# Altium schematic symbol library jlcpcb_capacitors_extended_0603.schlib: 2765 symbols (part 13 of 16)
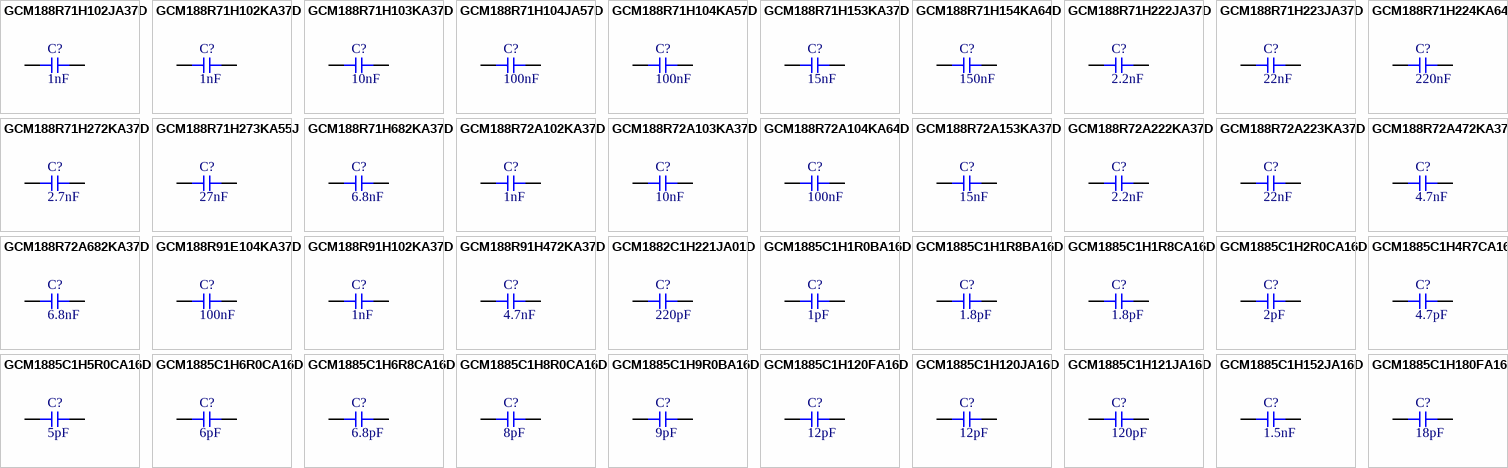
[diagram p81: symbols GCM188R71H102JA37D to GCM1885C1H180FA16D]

## GCM1885C1H152JA16D
designator C?  Capacitance: 1.5nF  (hidden comment: *)
Capacitor, Ceramic (MLCC), 1.5nF, ±5%, 50V, C0G, ±5%, SMD 0603; Manufacturer: Murata Electronics; Manufacturer Part Number: GCM1885C1H152JA16D
footprint CAP-0603 (0603 (1608M) Capacitor)
pins: 1, 2

## GCM1885C1H180FA16D
designator C?  Capacitance: 18pF  (hidden comment: *)
Capacitor, Ceramic (MLCC), 18pF, ±1%, 50V, C0G, ±1%, SMD 0603; Manufacturer: Murata Electronics; Manufacturer Part Number: GCM1885C1H180FA16D
footprint CAP-0603 (0603 (1608M) Capacitor)
pins: 1, 2

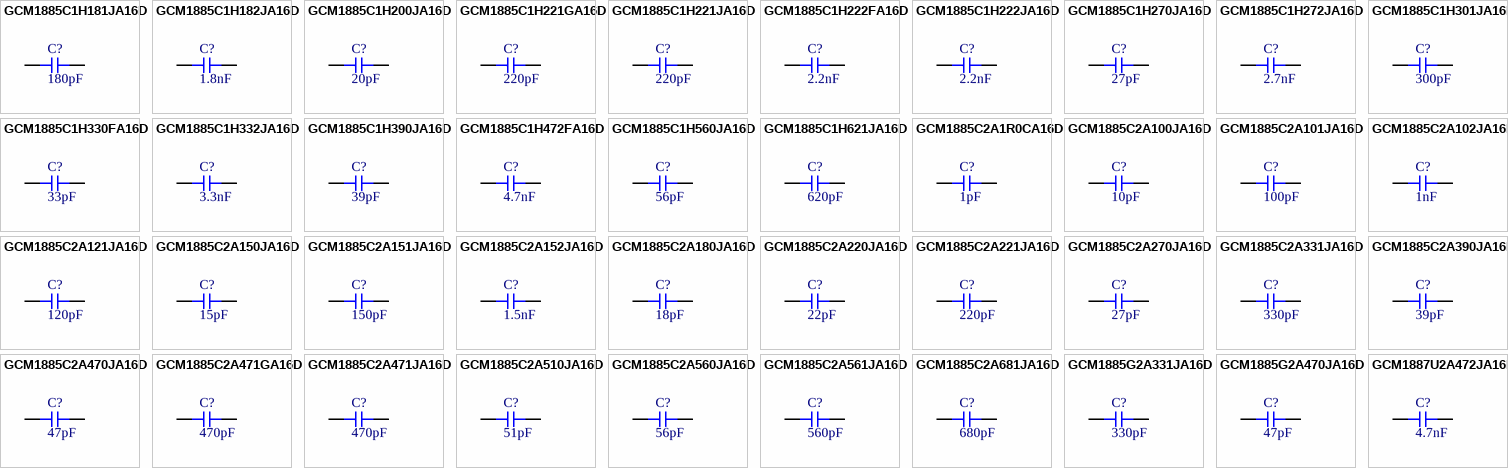
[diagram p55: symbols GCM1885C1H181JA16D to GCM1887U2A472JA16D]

## GCM1885C1H181JA16D
designator C?  Capacitance: 180pF  (hidden comment: *)
Capacitor, Ceramic (MLCC), 180pF, ±5%, 50V, C0G, ±5%, SMD 0603; Manufacturer: Murata Electronics; Manufacturer Part Number: GCM1885C1H181JA16D
footprint CAP-0603 (0603 (1608M) Capacitor)
pins: 1, 2

## GCM1885C1H182JA16D
designator C?  Capacitance: 1.8nF  (hidden comment: *)
Capacitor, Ceramic (MLCC), 1.8nF, ±5%, 50V, C0G, ±5%, SMD 0603; Manufacturer: Murata Electronics; Manufacturer Part Number: GCM1885C1H182JA16D
footprint CAP-0603 (0603 (1608M) Capacitor)
pins: 1, 2

## GCM1885C1H200JA16D
designator C?  Capacitance: 20pF  (hidden comment: *)
Capacitor, Ceramic (MLCC), 20pF, ±5%, 50V, C0G, ±5%, SMD 0603; Manufacturer: Murata Electronics; Manufacturer Part Number: GCM1885C1H200JA16D
footprint CAP-0603 (0603 (1608M) Capacitor)
pins: 1, 2

## GCM1885C1H221GA16D
designator C?  Capacitance: 220pF  (hidden comment: *)
Capacitor, Ceramic (MLCC), 220pF, ±2%, 50V, C0G, ±2%, SMD 0603; Manufacturer: Murata Electronics; Manufacturer Part Number: GCM1885C1H221GA16D
footprint CAP-0603 (0603 (1608M) Capacitor)
pins: 1, 2

## GCM1885C1H221JA16D
designator C?  Capacitance: 220pF  (hidden comment: *)
Capacitor, Ceramic (MLCC), 220pF, ±5%, 50V, C0G, ±5%, SMD 0603; Manufacturer: Murata Electronics; Manufacturer Part Number: GCM1885C1H221JA16D
footprint CAP-0603 (0603 (1608M) Capacitor)
pins: 1, 2

## GCM1885C1H222FA16D
designator C?  Capacitance: 2.2nF  (hidden comment: *)
Capacitor, Ceramic (MLCC), 2.2nF, ±1%, ±1%, SMD 0603; Manufacturer: Murata Electronics; Manufacturer Part Number: GCM1885C1H222FA16D
footprint CAP-0603 (0603 (1608M) Capacitor)
pins: 1, 2

## GCM1885C1H222JA16D
designator C?  Capacitance: 2.2nF  (hidden comment: *)
Capacitor, Ceramic (MLCC), 2.2nF, ±5%, 50V, C0G, ±5%, SMD 0603; Manufacturer: Murata Electronics; Manufacturer Part Number: GCM1885C1H222JA16D
footprint CAP-0603 (0603 (1608M) Capacitor)
pins: 1, 2

## GCM1885C1H270JA16D
designator C?  Capacitance: 27pF  (hidden comment: *)
Capacitor, Ceramic (MLCC), 27pF, ±5%, 50V, C0G, ±5%, SMD 0603; Manufacturer: Murata Electronics; Manufacturer Part Number: GCM1885C1H270JA16D
footprint CAP-0603 (0603 (1608M) Capacitor)
pins: 1, 2

## GCM1885C1H272JA16D
designator C?  Capacitance: 2.7nF  (hidden comment: *)
Capacitor, Ceramic (MLCC), 2.7nF, ±5%, 50V, C0G, ±5%, SMD 0603; Manufacturer: Murata Electronics; Manufacturer Part Number: GCM1885C1H272JA16D
footprint CAP-0603 (0603 (1608M) Capacitor)
pins: 1, 2

## GCM1885C1H301JA16D
designator C?  Capacitance: 300pF  (hidden comment: *)
Capacitor, Ceramic (MLCC), 300pF, ±5%, ±5%, SMD 0603; Manufacturer: Murata Electronics; Manufacturer Part Number: GCM1885C1H301JA16D
footprint CAP-0603 (0603 (1608M) Capacitor)
pins: 1, 2

## GCM1885C1H330FA16D
designator C?  Capacitance: 33pF  (hidden comment: *)
Capacitor, Ceramic (MLCC), 33pF, ±1%, 50V, C0G, ±1%, SMD 0603; Manufacturer: Murata Electronics; Manufacturer Part Number: GCM1885C1H330FA16D
footprint CAP-0603 (0603 (1608M) Capacitor)
pins: 1, 2

## GCM1885C1H332JA16D
designator C?  Capacitance: 3.3nF  (hidden comment: *)
Capacitor, Ceramic (MLCC), 3.3nF, ±5%, 50V, C0G, ±5%, SMD 0603; Manufacturer: Murata Electronics; Manufacturer Part Number: GCM1885C1H332JA16D
footprint CAP-0603 (0603 (1608M) Capacitor)
pins: 1, 2

## GCM1885C1H390JA16D
designator C?  Capacitance: 39pF  (hidden comment: *)
Capacitor, Ceramic (MLCC), 39pF, ±5%, 50V, C0G, ±5%, SMD 0603; Manufacturer: Murata Electronics; Manufacturer Part Number: GCM1885C1H390JA16D
footprint CAP-0603 (0603 (1608M) Capacitor)
pins: 1, 2

## GCM1885C1H472FA16D
designator C?  Capacitance: 4.7nF  (hidden comment: *)
Capacitor, Ceramic (MLCC), 4.7nF, ±1%, ±1%, SMD 0603; Manufacturer: Murata Electronics; Manufacturer Part Number: GCM1885C1H472FA16D
footprint CAP-0603 (0603 (1608M) Capacitor)
pins: 1, 2

## GCM1885C1H560JA16D
designator C?  Capacitance: 56pF  (hidden comment: *)
Capacitor, Ceramic (MLCC), 56pF, ±5%, 50V, C0G, ±5%, SMD 0603; Manufacturer: Murata Electronics; Manufacturer Part Number: GCM1885C1H560JA16D
footprint CAP-0603 (0603 (1608M) Capacitor)
pins: 1, 2

## GCM1885C1H621JA16D
designator C?  Capacitance: 620pF  (hidden comment: *)
Capacitor, Ceramic (MLCC), 620pF, ±5%, 50V, C0G, ±5%, SMD 0603; Manufacturer: Murata Electronics; Manufacturer Part Number: GCM1885C1H621JA16D
footprint CAP-0603 (0603 (1608M) Capacitor)
pins: 1, 2

## GCM1885C2A1R0CA16D
designator C?  Capacitance: 1pF  (hidden comment: *)
Capacitor, Ceramic (MLCC), 1pF, ±0.25pF, 100V, C0G, ±0.25pF, SMD 0603; Manufacturer: Murata Electronics; Manufacturer Part Number: GCM1885C2A1R0CA16D
footprint CAP-0603 (0603 (1608M) Capacitor)
pins: 1, 2

## GCM1885C2A100JA16D
designator C?  Capacitance: 10pF  (hidden comment: *)
Capacitor, Ceramic (MLCC), 10pF, ±5%, 100V, C0G, ±5%, SMD 0603; Manufacturer: Murata Electronics; Manufacturer Part Number: GCM1885C2A100JA16D
footprint CAP-0603 (0603 (1608M) Capacitor)
pins: 1, 2

## GCM1885C2A101JA16D
designator C?  Capacitance: 100pF  (hidden comment: *)
Capacitor, Ceramic (MLCC), 100pF, ±5%, 100V, C0G, ±5%, SMD 0603; Manufacturer: Murata Electronics; Manufacturer Part Number: GCM1885C2A101JA16D
footprint CAP-0603 (0603 (1608M) Capacitor)
pins: 1, 2

## GCM1885C2A102JA16D
designator C?  Capacitance: 1nF  (hidden comment: *)
Capacitor, Ceramic (MLCC), 1nF, ±5%, 100V, C0G, ±5%, SMD 0603; Manufacturer: Murata Electronics; Manufacturer Part Number: GCM1885C2A102JA16D
footprint CAP-0603 (0603 (1608M) Capacitor)
pins: 1, 2

## GCM1885C2A121JA16D
designator C?  Capacitance: 120pF  (hidden comment: *)
Capacitor, Ceramic (MLCC), 120pF, ±5%, ±5%, SMD 0603; Manufacturer: Murata Electronics; Manufacturer Part Number: GCM1885C2A121JA16D
footprint CAP-0603 (0603 (1608M) Capacitor)
pins: 1, 2

## GCM1885C2A150JA16D
designator C?  Capacitance: 15pF  (hidden comment: *)
Capacitor, Ceramic (MLCC), 15pF, ±5%, 100V, C0G, ±5%, SMD 0603; Manufacturer: Murata Electronics; Manufacturer Part Number: GCM1885C2A150JA16D
footprint CAP-0603 (0603 (1608M) Capacitor)
pins: 1, 2

## GCM1885C2A151JA16D
designator C?  Capacitance: 150pF  (hidden comment: *)
Capacitor, Ceramic (MLCC), 150pF, ±5%, 100V, C0G, ±5%, SMD 0603; Manufacturer: Murata Electronics; Manufacturer Part Number: GCM1885C2A151JA16D
footprint CAP-0603 (0603 (1608M) Capacitor)
pins: 1, 2

## GCM1885C2A152JA16D
designator C?  Capacitance: 1.5nF  (hidden comment: *)
Capacitor, Ceramic (MLCC), 1.5nF, ±5%, 100V, C0G, ±5%, SMD 0603; Manufacturer: Murata Electronics; Manufacturer Part Number: GCM1885C2A152JA16D
footprint CAP-0603 (0603 (1608M) Capacitor)
pins: 1, 2

## GCM1885C2A180JA16D
designator C?  Capacitance: 18pF  (hidden comment: *)
Capacitor, Ceramic (MLCC), 18pF, ±5%, ±5%, SMD 0603; Manufacturer: Murata Electronics; Manufacturer Part Number: GCM1885C2A180JA16D
footprint CAP-0603 (0603 (1608M) Capacitor)
pins: 1, 2

## GCM1885C2A220JA16D
designator C?  Capacitance: 22pF  (hidden comment: *)
Capacitor, Ceramic (MLCC), 22pF, ±5%, 100V, C0G, ±5%, SMD 0603; Manufacturer: Murata Electronics; Manufacturer Part Number: GCM1885C2A220JA16D
footprint CAP-0603 (0603 (1608M) Capacitor)
pins: 1, 2

## GCM1885C2A221JA16D
designator C?  Capacitance: 220pF  (hidden comment: *)
Capacitor, Ceramic (MLCC), 220pF, ±5%, 100V, C0G, ±5%, SMD 0603; Manufacturer: Murata Electronics; Manufacturer Part Number: GCM1885C2A221JA16D
footprint CAP-0603 (0603 (1608M) Capacitor)
pins: 1, 2

## GCM1885C2A270JA16D
designator C?  Capacitance: 27pF  (hidden comment: *)
Capacitor, Ceramic (MLCC), 27pF, ±5%, ±5%, SMD 0603; Manufacturer: Murata Electronics; Manufacturer Part Number: GCM1885C2A270JA16D
footprint CAP-0603 (0603 (1608M) Capacitor)
pins: 1, 2

## GCM1885C2A331JA16D
designator C?  Capacitance: 330pF  (hidden comment: *)
Capacitor, Ceramic (MLCC), 330pF, ±5%, 100V, C0G, ±5%, SMD 0603; Manufacturer: Murata Electronics; Manufacturer Part Number: GCM1885C2A331JA16D
footprint CAP-0603 (0603 (1608M) Capacitor)
pins: 1, 2

## GCM1885C2A390JA16D
designator C?  Capacitance: 39pF  (hidden comment: *)
Capacitor, Ceramic (MLCC), 39pF, ±5%, 100V, C0G, ±5%, SMD 0603; Manufacturer: Murata Electronics; Manufacturer Part Number: GCM1885C2A390JA16D
footprint CAP-0603 (0603 (1608M) Capacitor)
pins: 1, 2

## GCM1885C2A470JA16D
designator C?  Capacitance: 47pF  (hidden comment: *)
Capacitor, Ceramic (MLCC), 47pF, ±5%, 100V, C0G, ±5%, SMD 0603; Manufacturer: Murata Electronics; Manufacturer Part Number: GCM1885C2A470JA16D
footprint CAP-0603 (0603 (1608M) Capacitor)
pins: 1, 2

## GCM1885C2A471GA16D
designator C?  Capacitance: 470pF  (hidden comment: *)
Capacitor, Ceramic (MLCC), 470pF, ±2%, 100V, C0G, ±2%, SMD 0603; Manufacturer: Murata Electronics; Manufacturer Part Number: GCM1885C2A471GA16D
footprint CAP-0603 (0603 (1608M) Capacitor)
pins: 1, 2

## GCM1885C2A471JA16D
designator C?  Capacitance: 470pF  (hidden comment: *)
Capacitor, Ceramic (MLCC), 470pF, ±5%, 100V, C0G, ±5%, SMD 0603; Manufacturer: Murata Electronics; Manufacturer Part Number: GCM1885C2A471JA16D
footprint CAP-0603 (0603 (1608M) Capacitor)
pins: 1, 2

## GCM1885C2A510JA16D
designator C?  Capacitance: 51pF  (hidden comment: *)
Capacitor, Ceramic (MLCC), 51pF, ±5%, 100V, C0G, ±5%, SMD 0603; Manufacturer: Murata Electronics; Manufacturer Part Number: GCM1885C2A510JA16D
footprint CAP-0603 (0603 (1608M) Capacitor)
pins: 1, 2

## GCM1885C2A560JA16D
designator C?  Capacitance: 56pF  (hidden comment: *)
Capacitor, Ceramic (MLCC), 56pF, ±5%, 100V, C0G, ±5%, SMD 0603; Manufacturer: Murata Electronics; Manufacturer Part Number: GCM1885C2A560JA16D
footprint CAP-0603 (0603 (1608M) Capacitor)
pins: 1, 2

## GCM1885C2A561JA16D
designator C?  Capacitance: 560pF  (hidden comment: *)
Capacitor, Ceramic (MLCC), 560pF, ±5%, 100V, C0G, ±5%, SMD 0603; Manufacturer: Murata Electronics; Manufacturer Part Number: GCM1885C2A561JA16D
footprint CAP-0603 (0603 (1608M) Capacitor)
pins: 1, 2

## GCM1885C2A681JA16D
designator C?  Capacitance: 680pF  (hidden comment: *)
Capacitor, Ceramic (MLCC), 680pF, ±5%, 100V, C0G, ±5%, SMD 0603; Manufacturer: Murata Electronics; Manufacturer Part Number: GCM1885C2A681JA16D
footprint CAP-0603 (0603 (1608M) Capacitor)
pins: 1, 2

## GCM1885G2A331JA16D
designator C?  Capacitance: 330pF  (hidden comment: *)
Capacitor, Ceramic (MLCC), 330pF, ±5%, 100V, X8G, ±5%, SMD 0603; Manufacturer: Murata Electronics; Manufacturer Part Number: GCM1885G2A331JA16D
footprint CAP-0603 (0603 (1608M) Capacitor)
pins: 1, 2

## GCM1885G2A470JA16D
designator C?  Capacitance: 47pF  (hidden comment: *)
Capacitor, Ceramic (MLCC), 47pF, ±5%, 100V, X8G, ±5%, SMD 0603; Manufacturer: Murata Electronics; Manufacturer Part Number: GCM1885G2A470JA16D
footprint CAP-0603 (0603 (1608M) Capacitor)
pins: 1, 2

## GCM1887U2A472JA16D
designator C?  Capacitance: 4.7nF  (hidden comment: *)
Capacitor, Ceramic (MLCC), 4.7nF, ±5%, ±5%, SMD 0603; Manufacturer: Murata Electronics; Manufacturer Part Number: GCM1887U2A472JA16D
footprint CAP-0603 (0603 (1608M) Capacitor)
pins: 1, 2

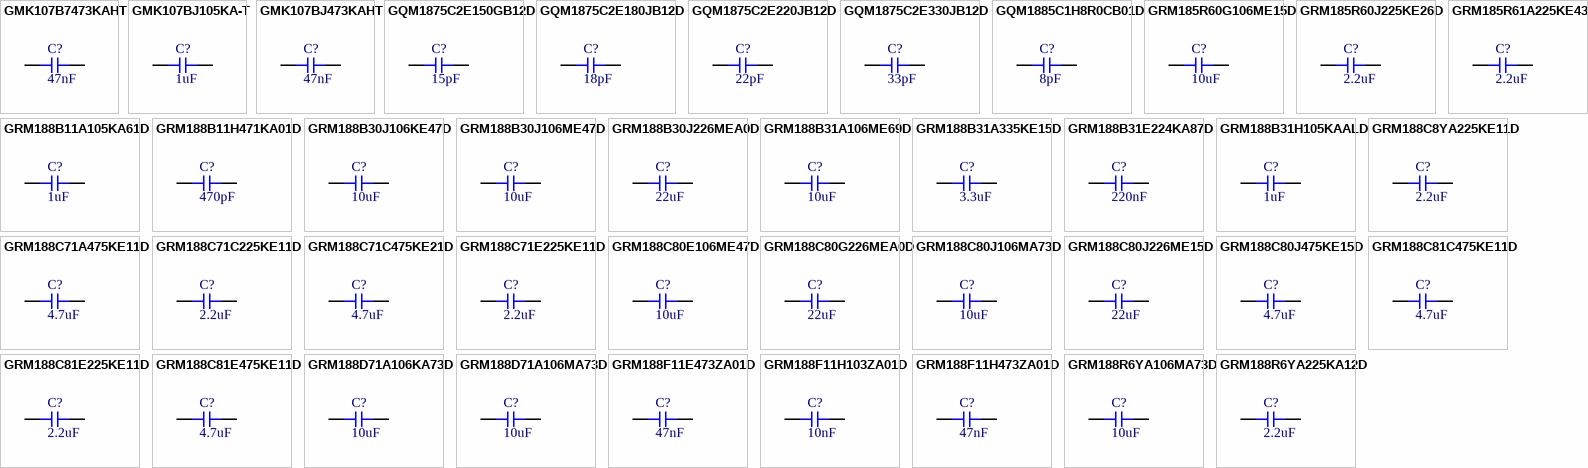
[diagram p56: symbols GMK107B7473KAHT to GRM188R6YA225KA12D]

## GMK107B7473KAHT
designator C?  Capacitance: 47nF  (hidden comment: *)
Capacitor, Ceramic (MLCC), 47nF, ±10%, 35V, X7R, ±10%, SMD 0603; Manufacturer: Taiyo Yuden; Manufacturer Part Number: GMK107B7473KAHT
footprint CAP-0603 (0603 (1608M) Capacitor)
pins: 1, 2

## GMK107BJ105KA-T
designator C?  Capacitance: 1uF  (hidden comment: *)
Capacitor, Ceramic (MLCC), 1uF, ±10%, 35V, X5R, ±10%, SMD 0603; Manufacturer: Taiyo Yuden; Manufacturer Part Number: GMK107BJ105KA-T
footprint CAP-0603 (0603 (1608M) Capacitor)
pins: 1, 2

## GMK107BJ473KAHT
designator C?  Capacitance: 47nF  (hidden comment: *)
Capacitor, Ceramic (MLCC), 47nF, ±10%, 35V, X5R, ±10%, SMD 0603; Manufacturer: Taiyo Yuden; Manufacturer Part Number: GMK107BJ473KAHT
footprint CAP-0603 (0603 (1608M) Capacitor)
pins: 1, 2

## GQM1875C2E150GB12D
designator C?  Capacitance: 15pF  (hidden comment: *)
Capacitor, Ceramic (MLCC), 15pF, ±2%, 250V, C0G, ±2%, SMD 0603; Manufacturer: Murata Electronics; Manufacturer Part Number: GQM1875C2E150GB12D
footprint CAP-0603 (0603 (1608M) Capacitor)
pins: 1, 2

## GQM1875C2E180JB12D
designator C?  Capacitance: 18pF  (hidden comment: *)
Capacitor, Ceramic (MLCC), 18pF, ±5%, 250V, C0G, ±5%, SMD 0603; Manufacturer: Murata Electronics; Manufacturer Part Number: GQM1875C2E180JB12D
footprint CAP-0603 (0603 (1608M) Capacitor)
pins: 1, 2

## GQM1875C2E220JB12D
designator C?  Capacitance: 22pF  (hidden comment: *)
Capacitor, Ceramic (MLCC), 22pF, ±5%, 250V, C0G, ±5%, SMD 0603; Manufacturer: Murata Electronics; Manufacturer Part Number: GQM1875C2E220JB12D
footprint CAP-0603 (0603 (1608M) Capacitor)
pins: 1, 2

## GQM1875C2E330JB12D
designator C?  Capacitance: 33pF  (hidden comment: *)
Capacitor, Ceramic (MLCC), 33pF, ±5%, ±5%, SMD 0603; Manufacturer: Murata Electronics; Manufacturer Part Number: GQM1875C2E330JB12D
footprint CAP-0603 (0603 (1608M) Capacitor)
pins: 1, 2

## GQM1885C1H8R0CB01D
designator C?  Capacitance: 8pF  (hidden comment: *)
Capacitor, Ceramic (MLCC), 8pF, ±0.25pF, 50V, C0G, ±0.25pF, SMD 0603; Manufacturer: Murata Electronics; Manufacturer Part Number: GQM1885C1H8R0CB01D
footprint CAP-0603 (0603 (1608M) Capacitor)
pins: 1, 2

## GRM185R60G106ME15D
designator C?  Capacitance: 10uF  (hidden comment: *)
Capacitor, Ceramic (MLCC), 10uF, ±20%, ±20%, SMD 0603; Manufacturer: Murata Electronics; Manufacturer Part Number: GRM185R60G106ME15D
footprint CAP-0603 (0603 (1608M) Capacitor)
pins: 1, 2

## GRM185R60J225KE26D
designator C?  Capacitance: 2.2uF  (hidden comment: *)
Capacitor, Ceramic (MLCC), 2.2uF, ±10%, ±10%, SMD 0603; Manufacturer: Murata Electronics; Manufacturer Part Number: GRM185R60J225KE26D
footprint CAP-0603 (0603 (1608M) Capacitor)
pins: 1, 2

## GRM185R61A225KE43D
designator C?  Capacitance: 2.2uF  (hidden comment: *)
Capacitor, Ceramic (MLCC), 2.2uF, ±10%, 10V, X5R, ±10%, SMD 0603; Manufacturer: Murata Electronics; Manufacturer Part Number: GRM185R61A225KE43D
footprint CAP-0603 (0603 (1608M) Capacitor)
pins: 1, 2

## GRM188B11A105KA61D
designator C?  Capacitance: 1uF  (hidden comment: *)
Capacitor, Ceramic (MLCC), 1uF, ±10%, 10V, B, ±10%, SMD 0603; Manufacturer: Murata Electronics; Manufacturer Part Number: GRM188B11A105KA61D
footprint CAP-0603 (0603 (1608M) Capacitor)
pins: 1, 2

## GRM188B11H471KA01D
designator C?  Capacitance: 470pF  (hidden comment: *)
Capacitor, Ceramic (MLCC), 470pF, ±10%, 50V, B, ±10%, SMD 0603; Manufacturer: Murata Electronics; Manufacturer Part Number: GRM188B11H471KA01D
footprint CAP-0603 (0603 (1608M) Capacitor)
pins: 1, 2

## GRM188B30J106KE47D
designator C?  Capacitance: 10uF  (hidden comment: *)
Capacitor, Ceramic (MLCC), 10uF, ±10%, 6.3V, B, ±10%, SMD 0603; Manufacturer: Murata Electronics; Manufacturer Part Number: GRM188B30J106KE47D
footprint CAP-0603 (0603 (1608M) Capacitor)
pins: 1, 2

## GRM188B30J106ME47D
designator C?  Capacitance: 10uF  (hidden comment: *)
Capacitor, Ceramic (MLCC), 10uF, ±20%, 6.3V, B, ±20%, SMD 0603; Manufacturer: Murata Electronics; Manufacturer Part Number: GRM188B30J106ME47D
footprint CAP-0603 (0603 (1608M) Capacitor)
pins: 1, 2

## GRM188B30J226MEA0D
designator C?  Capacitance: 22uF  (hidden comment: *)
Capacitor, Ceramic (MLCC), 22uF, ±20%, 6.3V, B, ±20%, SMD 0603; Manufacturer: Murata Electronics; Manufacturer Part Number: GRM188B30J226MEA0D
footprint CAP-0603 (0603 (1608M) Capacitor)
pins: 1, 2

## GRM188B31A106ME69D
designator C?  Capacitance: 10uF  (hidden comment: *)
Capacitor, Ceramic (MLCC), 10uF, ±20%, 10V, B, ±20%, SMD 0603; Manufacturer: Murata Electronics; Manufacturer Part Number: GRM188B31A106ME69D
footprint CAP-0603 (0603 (1608M) Capacitor)
pins: 1, 2

## GRM188B31A335KE15D
designator C?  Capacitance: 3.3uF  (hidden comment: *)
Capacitor, Ceramic (MLCC), 3.3uF, ±10%, 10V, B, ±10%, SMD 0603; Manufacturer: Murata Electronics; Manufacturer Part Number: GRM188B31A335KE15D
footprint CAP-0603 (0603 (1608M) Capacitor)
pins: 1, 2

## GRM188B31E224KA87D
designator C?  Capacitance: 220nF  (hidden comment: *)
Capacitor, Ceramic (MLCC), 220nF, ±10%, 25V, B, ±10%, SMD 0603; Manufacturer: Murata Electronics; Manufacturer Part Number: GRM188B31E224KA87D
footprint CAP-0603 (0603 (1608M) Capacitor)
pins: 1, 2

## GRM188B31H105KAALD
designator C?  Capacitance: 1uF  (hidden comment: *)
Capacitor, Ceramic (MLCC), 1uF, ±10%, ±10%, SMD 0603; Manufacturer: Murata Electronics; Manufacturer Part Number: GRM188B31H105KAALD
footprint CAP-0603 (0603 (1608M) Capacitor)
pins: 1, 2

## GRM188C8YA225KE11D
designator C?  Capacitance: 2.2uF  (hidden comment: *)
Capacitor, Ceramic (MLCC), 2.2uF, ±10%, 35V, X6S, ±10%, SMD 0603; Manufacturer: Murata Electronics; Manufacturer Part Number: GRM188C8YA225KE11D
footprint CAP-0603 (0603 (1608M) Capacitor)
pins: 1, 2

## GRM188C71A475KE11D
designator C?  Capacitance: 4.7uF  (hidden comment: *)
Capacitor, Ceramic (MLCC), 4.7uF, ±10%, 10V, X7S, ±10%, SMD 0603; Manufacturer: Murata Electronics; Manufacturer Part Number: GRM188C71A475KE11D
footprint CAP-0603 (0603 (1608M) Capacitor)
pins: 1, 2

## GRM188C71C225KE11D
designator C?  Capacitance: 2.2uF  (hidden comment: *)
Capacitor, Ceramic (MLCC), 2.2uF, ±10%, 16V, X7S, ±10%, SMD 0603; Manufacturer: Murata Electronics; Manufacturer Part Number: GRM188C71C225KE11D
footprint CAP-0603 (0603 (1608M) Capacitor)
pins: 1, 2

## GRM188C71C475KE21D
designator C?  Capacitance: 4.7uF  (hidden comment: *)
Capacitor, Ceramic (MLCC), 4.7uF, ±10%, 16V, X7S, ±10%, SMD 0603; Manufacturer: Murata Electronics; Manufacturer Part Number: GRM188C71C475KE21D
footprint CAP-0603 (0603 (1608M) Capacitor)
pins: 1, 2

## GRM188C71E225KE11D
designator C?  Capacitance: 2.2uF  (hidden comment: *)
Capacitor, Ceramic (MLCC), 2.2uF, ±10%, 25V, X7S, ±10%, SMD 0603; Manufacturer: Murata Electronics; Manufacturer Part Number: GRM188C71E225KE11D
footprint CAP-0603 (0603 (1608M) Capacitor)
pins: 1, 2

## GRM188C80E106ME47D
designator C?  Capacitance: 10uF  (hidden comment: *)
Capacitor, Ceramic (MLCC), 10uF, ±20%, 2.5V, X6S, ±20%, SMD 0603; Manufacturer: Murata Electronics; Manufacturer Part Number: GRM188C80E106ME47D
footprint CAP-0603 (0603 (1608M) Capacitor)
pins: 1, 2

## GRM188C80G226MEA0D
designator C?  Capacitance: 22uF  (hidden comment: *)
Capacitor, Ceramic (MLCC), 22uF, ±20%, 4V, X6S, ±20%, SMD 0603; Manufacturer: Murata Electronics; Manufacturer Part Number: GRM188C80G226MEA0D
footprint CAP-0603 (0603 (1608M) Capacitor)
pins: 1, 2

## GRM188C80J106MA73D
designator C?  Capacitance: 10uF  (hidden comment: *)
Capacitor, Ceramic (MLCC), 10uF, ±20%, 6.3V, X6S, ±20%, SMD 0603; Manufacturer: Murata Electronics; Manufacturer Part Number: GRM188C80J106MA73D
footprint CAP-0603 (0603 (1608M) Capacitor)
pins: 1, 2

## GRM188C80J226ME15D
designator C?  Capacitance: 22uF  (hidden comment: *)
Capacitor, Ceramic (MLCC), 22uF, ±20%, 6.3V, X6S, ±20%, SMD 0603; Manufacturer: Murata Electronics; Manufacturer Part Number: GRM188C80J226ME15D
footprint CAP-0603 (0603 (1608M) Capacitor)
pins: 1, 2

## GRM188C80J475KE15D
designator C?  Capacitance: 4.7uF  (hidden comment: *)
Capacitor, Ceramic (MLCC), 4.7uF, ±10%, 6.3V, X6S, ±10%, SMD 0603; Manufacturer: Murata Electronics; Manufacturer Part Number: GRM188C80J475KE15D
footprint CAP-0603 (0603 (1608M) Capacitor)
pins: 1, 2

## GRM188C81C475KE11D
designator C?  Capacitance: 4.7uF  (hidden comment: *)
Capacitor, Ceramic (MLCC), 4.7uF, ±10%, 16V, X6S, ±10%, SMD 0603; Manufacturer: Murata Electronics; Manufacturer Part Number: GRM188C81C475KE11D
footprint CAP-0603 (0603 (1608M) Capacitor)
pins: 1, 2

## GRM188C81E225KE11D
designator C?  Capacitance: 2.2uF  (hidden comment: *)
Capacitor, Ceramic (MLCC), 2.2uF, ±10%, 25V, X6S, ±10%, SMD 0603; Manufacturer: Murata Electronics; Manufacturer Part Number: GRM188C81E225KE11D
footprint CAP-0603 (0603 (1608M) Capacitor)
pins: 1, 2

## GRM188C81E475KE11D
designator C?  Capacitance: 4.7uF  (hidden comment: *)
Capacitor, Ceramic (MLCC), 4.7uF, ±10%, ±10%, SMD 0603; Manufacturer: Murata Electronics; Manufacturer Part Number: GRM188C81E475KE11D
footprint CAP-0603 (0603 (1608M) Capacitor)
pins: 1, 2

## GRM188D71A106KA73D
designator C?  Capacitance: 10uF  (hidden comment: *)
Capacitor, Ceramic (MLCC), 10uF, ±10%, 10V, X7T, ±10%, SMD 0603; Manufacturer: Murata Electronics; Manufacturer Part Number: GRM188D71A106KA73D
footprint CAP-0603 (0603 (1608M) Capacitor)
pins: 1, 2

## GRM188D71A106MA73D
designator C?  Capacitance: 10uF  (hidden comment: *)
Capacitor, Ceramic (MLCC), 10uF, ±20%, 10V, X7T, ±20%, SMD 0603; Manufacturer: Murata Electronics; Manufacturer Part Number: GRM188D71A106MA73D
footprint CAP-0603 (0603 (1608M) Capacitor)
pins: 1, 2

## GRM188F11E473ZA01D
designator C?  Capacitance: 47nF  (hidden comment: *)
Capacitor, Ceramic (MLCC), 47nF, 25V, SMD 0603; Manufacturer: Murata Electronics; Manufacturer Part Number: GRM188F11E473ZA01D; Temperature Rating: -20%~+80%
footprint CAP-0603 (0603 (1608M) Capacitor)
pins: 1, 2

## GRM188F11H103ZA01D
designator C?  Capacitance: 10nF  (hidden comment: *)
Capacitor, Ceramic (MLCC), 10nF, 50V, SMD 0603; Manufacturer: Murata Electronics; Manufacturer Part Number: GRM188F11H103ZA01D; Temperature Rating: -20%~+80%
footprint CAP-0603 (0603 (1608M) Capacitor)
pins: 1, 2

## GRM188F11H473ZA01D
designator C?  Capacitance: 47nF  (hidden comment: *)
Capacitor, Ceramic (MLCC), 47nF, 50V, SMD 0603; Manufacturer: Murata Electronics; Manufacturer Part Number: GRM188F11H473ZA01D; Temperature Rating: -20%~+80%
footprint CAP-0603 (0603 (1608M) Capacitor)
pins: 1, 2

## GRM188R6YA106MA73D
designator C?  Capacitance: 10uF  (hidden comment: *)
Capacitor, Ceramic (MLCC), 10uF, ±20%, 35V, ±20%, SMD 0603; Manufacturer: Murata Electronics; Manufacturer Part Number: GRM188R6YA106MA73D
footprint CAP-0603 (0603 (1608M) Capacitor)
pins: 1, 2

## GRM188R6YA225KA12D
designator C?  Capacitance: 2.2uF  (hidden comment: *)
Capacitor, Ceramic (MLCC), 2.2uF, ±10%, 35V, X5R, ±10%, SMD 0603; Manufacturer: Murata Electronics; Manufacturer Part Number: GRM188R6YA225KA12D
footprint CAP-0603 (0603 (1608M) Capacitor)
pins: 1, 2

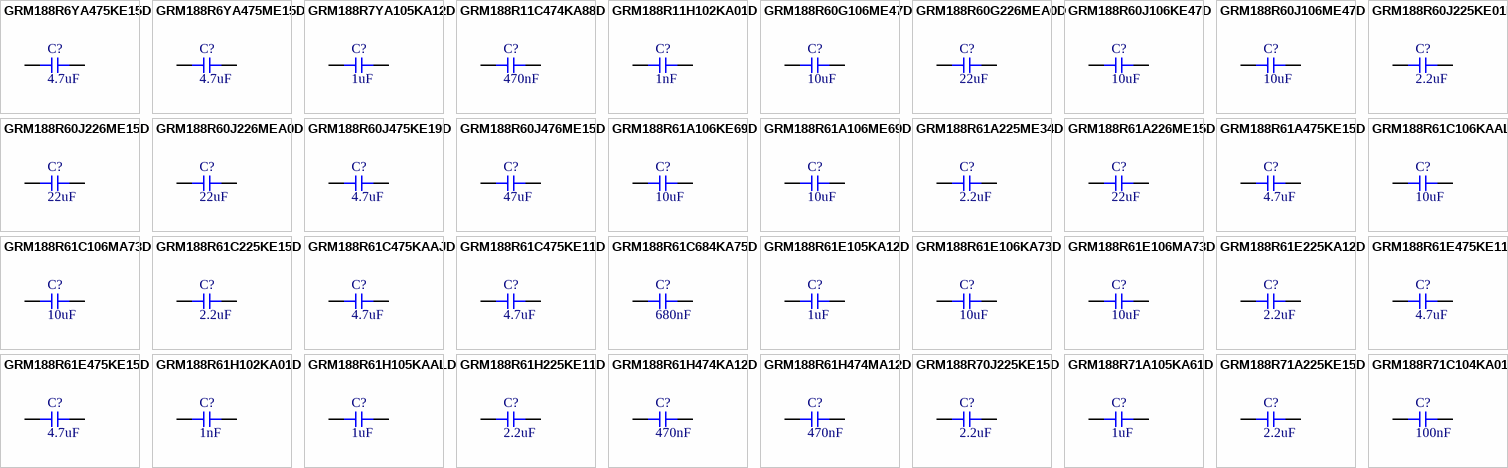
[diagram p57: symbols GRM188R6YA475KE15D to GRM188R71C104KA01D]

## GRM188R6YA475KE15D
designator C?  Capacitance: 4.7uF  (hidden comment: *)
Capacitor, Ceramic (MLCC), 4.7uF, ±10%, 35V, X5R, ±10%, SMD 0603; Manufacturer: Murata Electronics; Manufacturer Part Number: GRM188R6YA475KE15D
footprint CAP-0603 (0603 (1608M) Capacitor)
pins: 1, 2

## GRM188R6YA475ME15D
designator C?  Capacitance: 4.7uF  (hidden comment: *)
Capacitor, Ceramic (MLCC), 4.7uF, ±20%, 35V, X5R, ±20%, SMD 0603; Manufacturer: Murata Electronics; Manufacturer Part Number: GRM188R6YA475ME15D
footprint CAP-0603 (0603 (1608M) Capacitor)
pins: 1, 2

## GRM188R7YA105KA12D
designator C?  Capacitance: 1uF  (hidden comment: *)
Capacitor, Ceramic (MLCC), 1uF, ±10%, 35V, X7R, ±10%, SMD 0603; Manufacturer: Murata Electronics; Manufacturer Part Number: GRM188R7YA105KA12D
footprint CAP-0603 (0603 (1608M) Capacitor)
pins: 1, 2

## GRM188R11C474KA88D
designator C?  Capacitance: 470nF  (hidden comment: *)
Capacitor, Ceramic (MLCC), 470nF, ±10%, 16V, R, ±10%, SMD 0603; Manufacturer: Murata Electronics; Manufacturer Part Number: GRM188R11C474KA88D
footprint CAP-0603 (0603 (1608M) Capacitor)
pins: 1, 2

## GRM188R11H102KA01D
designator C?  Capacitance: 1nF  (hidden comment: *)
Capacitor, Ceramic (MLCC), 1nF, ±10%, 50V, R, ±10%, SMD 0603; Manufacturer: Murata Electronics; Manufacturer Part Number: GRM188R11H102KA01D
footprint CAP-0603 (0603 (1608M) Capacitor)
pins: 1, 2

## GRM188R60G106ME47D
designator C?  Capacitance: 10uF  (hidden comment: *)
Capacitor, Ceramic (MLCC), 10uF, ±20%, 4V, X5R, ±20%, SMD 0603; Manufacturer: Murata Electronics; Manufacturer Part Number: GRM188R60G106ME47D
footprint CAP-0603 (0603 (1608M) Capacitor)
pins: 1, 2

## GRM188R60G226MEA0D
designator C?  Capacitance: 22uF  (hidden comment: *)
Capacitor, Ceramic (MLCC), 22uF, ±20%, ±20%, SMD 0603; Manufacturer: Murata Electronics; Manufacturer Part Number: GRM188R60G226MEA0D
footprint CAP-0603 (0603 (1608M) Capacitor)
pins: 1, 2

## GRM188R60J106KE47D
designator C?  Capacitance: 10uF  (hidden comment: *)
Capacitor, Ceramic (MLCC), 10uF, ±10%, 6.3V, X5R, ±10%, SMD 0603; Manufacturer: Murata Electronics; Manufacturer Part Number: GRM188R60J106KE47D
footprint CAP-0603 (0603 (1608M) Capacitor)
pins: 1, 2

## GRM188R60J106ME47D
designator C?  Capacitance: 10uF  (hidden comment: *)
Capacitor, Ceramic (MLCC), 10uF, ±20%, 6.3V, X5R, ±20%, SMD 0603; Manufacturer: Murata Electronics; Manufacturer Part Number: GRM188R60J106ME47D
footprint CAP-0603 (0603 (1608M) Capacitor)
pins: 1, 2

## GRM188R60J225KE01D
designator C?  Capacitance: 2.2uF  (hidden comment: *)
Capacitor, Ceramic (MLCC), 2.2uF, ±10%, 6.3V, X5R, ±10%, SMD 0603; Manufacturer: Murata Electronics; Manufacturer Part Number: GRM188R60J225KE01D
footprint CAP-0603 (0603 (1608M) Capacitor)
pins: 1, 2

## GRM188R60J226ME15D
designator C?  Capacitance: 22uF  (hidden comment: *)
Capacitor, Ceramic (MLCC), 22uF, ±20%, 6.3V, X5R, ±20%, SMD 0603; Manufacturer: Murata Electronics; Manufacturer Part Number: GRM188R60J226ME15D
footprint CAP-0603 (0603 (1608M) Capacitor)
pins: 1, 2

## GRM188R60J226MEA0D
designator C?  Capacitance: 22uF  (hidden comment: *)
Capacitor, Ceramic (MLCC), 22uF, ±20%, 6.3V, X5R, ±20%, SMD 0603; Manufacturer: Murata Electronics; Manufacturer Part Number: GRM188R60J226MEA0D
footprint CAP-0603 (0603 (1608M) Capacitor)
pins: 1, 2

## GRM188R60J475KE19D
designator C?  Capacitance: 4.7uF  (hidden comment: *)
Capacitor, Ceramic (MLCC), 4.7uF, ±10%, 6.3V, X5R, ±10%, SMD 0603; Manufacturer: Murata Electronics; Manufacturer Part Number: GRM188R60J475KE19D
footprint CAP-0603 (0603 (1608M) Capacitor)
pins: 1, 2

## GRM188R60J476ME15D
designator C?  Capacitance: 47uF  (hidden comment: *)
Capacitor, Ceramic (MLCC), 47uF, ±20%, 6.3V, X5R, ±20%, SMD 0603; Manufacturer: Murata Electronics; Manufacturer Part Number: GRM188R60J476ME15D
footprint CAP-0603 (0603 (1608M) Capacitor)
pins: 1, 2

## GRM188R61A106KE69D
designator C?  Capacitance: 10uF  (hidden comment: *)
Capacitor, Ceramic (MLCC), 10uF, ±10%, 10V, X5R, ±10%, SMD 0603; Manufacturer: Murata Electronics; Manufacturer Part Number: GRM188R61A106KE69D
footprint CAP-0603 (0603 (1608M) Capacitor)
pins: 1, 2

## GRM188R61A106ME69D
designator C?  Capacitance: 10uF  (hidden comment: *)
Capacitor, Ceramic (MLCC), 10uF, ±20%, 10V, X5R, ±20%, SMD 0603; Manufacturer: Murata Electronics; Manufacturer Part Number: GRM188R61A106ME69D
footprint CAP-0603 (0603 (1608M) Capacitor)
pins: 1, 2

## GRM188R61A225ME34D
designator C?  Capacitance: 2.2uF  (hidden comment: *)
Capacitor, Ceramic (MLCC), 2.2uF, ±20%, 10V, X5R, ±20%, SMD 0603; Manufacturer: Murata Electronics; Manufacturer Part Number: GRM188R61A225ME34D
footprint CAP-0603 (0603 (1608M) Capacitor)
pins: 1, 2

## GRM188R61A226ME15D
designator C?  Capacitance: 22uF  (hidden comment: *)
Capacitor, Ceramic (MLCC), 22uF, ±20%, 10V, X5R, ±20%, SMD 0603; Manufacturer: Murata Electronics; Manufacturer Part Number: GRM188R61A226ME15D
footprint CAP-0603 (0603 (1608M) Capacitor)
pins: 1, 2

## GRM188R61A475KE15D
designator C?  Capacitance: 4.7uF  (hidden comment: *)
Capacitor, Ceramic (MLCC), 4.7uF, ±10%, 10V, X5R, ±10%, SMD 0603; Manufacturer: Murata Electronics; Manufacturer Part Number: GRM188R61A475KE15D
footprint CAP-0603 (0603 (1608M) Capacitor)
pins: 1, 2

## GRM188R61C106KAALD
designator C?  Capacitance: 10uF  (hidden comment: *)
Capacitor, Ceramic (MLCC), 10uF, ±10%, 16V, X5R, ±10%, SMD 0603; Manufacturer: Murata Electronics; Manufacturer Part Number: GRM188R61C106KAALD
footprint CAP-0603 (0603 (1608M) Capacitor)
pins: 1, 2

## GRM188R61C106MA73D
designator C?  Capacitance: 10uF  (hidden comment: *)
Capacitor, Ceramic (MLCC), 10uF, ±20%, 16V, X5R, ±20%, SMD 0603; Manufacturer: Murata Electronics; Manufacturer Part Number: GRM188R61C106MA73D
footprint CAP-0603 (0603 (1608M) Capacitor)
pins: 1, 2

## GRM188R61C225KE15D
designator C?  Capacitance: 2.2uF  (hidden comment: *)
Capacitor, Ceramic (MLCC), 2.2uF, ±10%, 16V, X5R, ±10%, SMD 0603; Manufacturer: Murata Electronics; Manufacturer Part Number: GRM188R61C225KE15D
footprint CAP-0603 (0603 (1608M) Capacitor)
pins: 1, 2

## GRM188R61C475KAAJD
designator C?  Capacitance: 4.7uF  (hidden comment: *)
Capacitor, Ceramic (MLCC), 4.7uF, ±10%, 16V, X5R, ±10%, SMD 0603; Manufacturer: Murata Electronics; Manufacturer Part Number: GRM188R61C475KAAJD
footprint CAP-0603 (0603 (1608M) Capacitor)
pins: 1, 2

## GRM188R61C475KE11D
designator C?  Capacitance: 4.7uF  (hidden comment: *)
Capacitor, Ceramic (MLCC), 4.7uF, ±10%, 16V, X5R, ±10%, SMD 0603; Manufacturer: Murata Electronics; Manufacturer Part Number: GRM188R61C475KE11D
footprint CAP-0603 (0603 (1608M) Capacitor)
pins: 1, 2

## GRM188R61C684KA75D
designator C?  Capacitance: 680nF  (hidden comment: *)
Capacitor, Ceramic (MLCC), 680nF, ±10%, 16V, X5R, ±10%, SMD 0603; Manufacturer: Murata Electronics; Manufacturer Part Number: GRM188R61C684KA75D
footprint CAP-0603 (0603 (1608M) Capacitor)
pins: 1, 2

## GRM188R61E105KA12D
designator C?  Capacitance: 1uF  (hidden comment: *)
Capacitor, Ceramic (MLCC), 1uF, ±10%, 25V, X5R, ±10%, SMD 0603; Manufacturer: Murata Electronics; Manufacturer Part Number: GRM188R61E105KA12D
footprint CAP-0603 (0603 (1608M) Capacitor)
pins: 1, 2

## GRM188R61E106KA73D
designator C?  Capacitance: 10uF  (hidden comment: *)
Capacitor, Ceramic (MLCC), 10uF, ±10%, 25V, X5R, ±10%, SMD 0603; Manufacturer: Murata Electronics; Manufacturer Part Number: GRM188R61E106KA73D
footprint CAP-0603 (0603 (1608M) Capacitor)
pins: 1, 2

## GRM188R61E106MA73D
designator C?  Capacitance: 10uF  (hidden comment: *)
Capacitor, Ceramic (MLCC), 10uF, ±20%, 25V, X5R, ±20%, SMD 0603; Manufacturer: Murata Electronics; Manufacturer Part Number: GRM188R61E106MA73D
footprint CAP-0603 (0603 (1608M) Capacitor)
pins: 1, 2

## GRM188R61E225KA12D
designator C?  Capacitance: 2.2uF  (hidden comment: *)
Capacitor, Ceramic (MLCC), 2.2uF, ±10%, 25V, X5R, ±10%, SMD 0603; Manufacturer: Murata Electronics; Manufacturer Part Number: GRM188R61E225KA12D
footprint CAP-0603 (0603 (1608M) Capacitor)
pins: 1, 2

## GRM188R61E475KE11D
designator C?  Capacitance: 4.7uF  (hidden comment: *)
Capacitor, Ceramic (MLCC), 4.7uF, ±10%, 25V, X5R, ±10%, SMD 0603; Manufacturer: Murata Electronics; Manufacturer Part Number: GRM188R61E475KE11D
footprint CAP-0603 (0603 (1608M) Capacitor)
pins: 1, 2

## GRM188R61E475KE15D
designator C?  Capacitance: 4.7uF  (hidden comment: *)
Capacitor, Ceramic (MLCC), 4.7uF, ±10%, 25V, X5R, ±10%, SMD 0603; Manufacturer: Murata Electronics; Manufacturer Part Number: GRM188R61E475KE15D
footprint CAP-0603 (0603 (1608M) Capacitor)
pins: 1, 2

## GRM188R61H102KA01D
designator C?  Capacitance: 1nF  (hidden comment: *)
Capacitor, Ceramic (MLCC), 1nF, ±10%, 50V, X5R, ±10%, SMD 0603; Manufacturer: Murata Electronics; Manufacturer Part Number: GRM188R61H102KA01D
footprint CAP-0603 (0603 (1608M) Capacitor)
pins: 1, 2

## GRM188R61H105KAALD
designator C?  Capacitance: 1uF  (hidden comment: *)
Capacitor, Ceramic (MLCC), 1uF, ±10%, 50V, X5R, ±10%, SMD 0603; Manufacturer: Murata Electronics; Manufacturer Part Number: GRM188R61H105KAALD
footprint CAP-0603 (0603 (1608M) Capacitor)
pins: 1, 2

## GRM188R61H225KE11D
designator C?  Capacitance: 2.2uF  (hidden comment: *)
Capacitor, Ceramic (MLCC), 2.2uF, ±10%, 50V, X5R, ±10%, SMD 0603; Manufacturer: Murata Electronics; Manufacturer Part Number: GRM188R61H225KE11D
footprint CAP-0603 (0603 (1608M) Capacitor)
pins: 1, 2

## GRM188R61H474KA12D
designator C?  Capacitance: 470nF  (hidden comment: *)
Capacitor, Ceramic (MLCC), 470nF, ±10%, 50V, X5R, ±10%, SMD 0603; Manufacturer: Murata Electronics; Manufacturer Part Number: GRM188R61H474KA12D
footprint CAP-0603 (0603 (1608M) Capacitor)
pins: 1, 2

## GRM188R61H474MA12D
designator C?  Capacitance: 470nF  (hidden comment: *)
Capacitor, Ceramic (MLCC), 470nF, ±20%, 50V, X5R, ±20%, SMD 0603; Manufacturer: Murata Electronics; Manufacturer Part Number: GRM188R61H474MA12D
footprint CAP-0603 (0603 (1608M) Capacitor)
pins: 1, 2

## GRM188R70J225KE15D
designator C?  Capacitance: 2.2uF  (hidden comment: *)
Capacitor, Ceramic (MLCC), 2.2uF, ±10%, 6.3V, X7R, ±10%, SMD 0603; Manufacturer: Murata Electronics; Manufacturer Part Number: GRM188R70J225KE15D
footprint CAP-0603 (0603 (1608M) Capacitor)
pins: 1, 2

## GRM188R71A105KA61D
designator C?  Capacitance: 1uF  (hidden comment: *)
Capacitor, Ceramic (MLCC), 1uF, ±10%, 10V, X7R, ±10%, SMD 0603; Manufacturer: Murata Electronics; Manufacturer Part Number: GRM188R71A105KA61D
footprint CAP-0603 (0603 (1608M) Capacitor)
pins: 1, 2

## GRM188R71A225KE15D
designator C?  Capacitance: 2.2uF  (hidden comment: *)
Capacitor, Ceramic (MLCC), 2.2uF, ±10%, 10V, X7R, ±10%, SMD 0603; Manufacturer: Murata Electronics; Manufacturer Part Number: GRM188R71A225KE15D
footprint CAP-0603 (0603 (1608M) Capacitor)
pins: 1, 2

## GRM188R71C104KA01D
designator C?  Capacitance: 100nF  (hidden comment: *)
Capacitor, Ceramic (MLCC), 100nF, ±10%, 16V, X7R, ±10%, SMD 0603; Manufacturer: Murata Electronics; Manufacturer Part Number: GRM188R71C104KA01D
footprint CAP-0603 (0603 (1608M) Capacitor)
pins: 1, 2

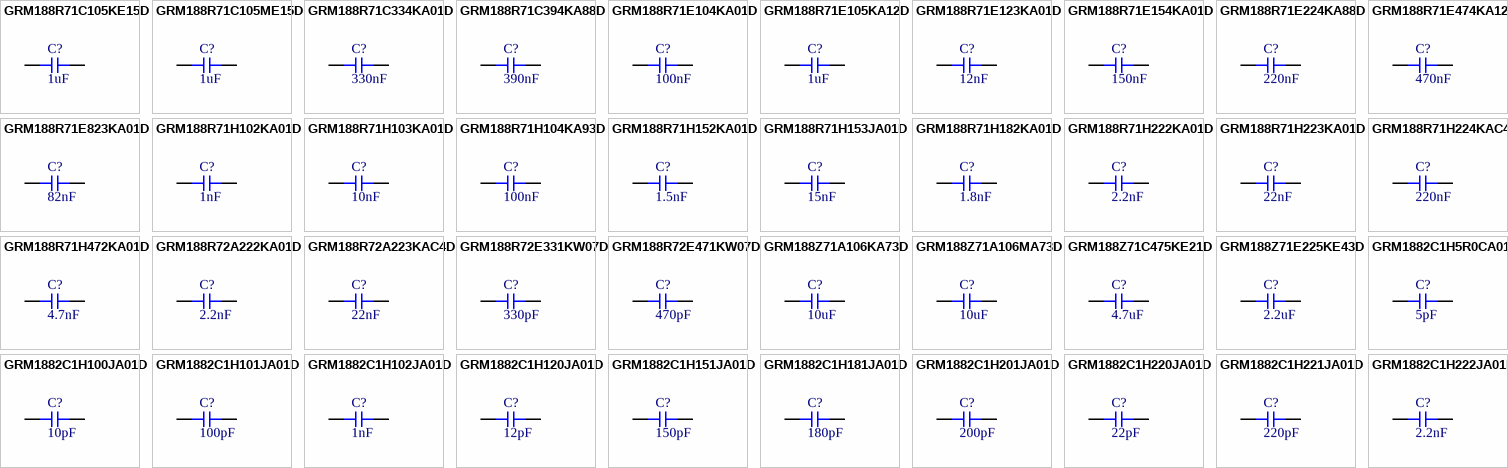
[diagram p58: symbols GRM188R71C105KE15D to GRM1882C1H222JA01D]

## GRM188R71C105KE15D
designator C?  Capacitance: 1uF  (hidden comment: *)
Capacitor, Ceramic (MLCC), 1uF, ±10%, 16V, X7R, ±10%, SMD 0603; Manufacturer: Murata Electronics; Manufacturer Part Number: GRM188R71C105KE15D
footprint CAP-0603 (0603 (1608M) Capacitor)
pins: 1, 2

## GRM188R71C105ME15D
designator C?  Capacitance: 1uF  (hidden comment: *)
Capacitor, Ceramic (MLCC), 1uF, ±20%, 16V, X7R, ±20%, SMD 0603; Manufacturer: Murata Electronics; Manufacturer Part Number: GRM188R71C105ME15D
footprint CAP-0603 (0603 (1608M) Capacitor)
pins: 1, 2

## GRM188R71C334KA01D
designator C?  Capacitance: 330nF  (hidden comment: *)
Capacitor, Ceramic (MLCC), 330nF, ±10%, 16V, X7R, ±10%, SMD 0603; Manufacturer: Murata Electronics; Manufacturer Part Number: GRM188R71C334KA01D
footprint CAP-0603 (0603 (1608M) Capacitor)
pins: 1, 2

## GRM188R71C394KA88D
designator C?  Capacitance: 390nF  (hidden comment: *)
Capacitor, Ceramic (MLCC), 390nF, ±10%, 16V, X7R, ±10%, SMD 0603; Manufacturer: Murata Electronics; Manufacturer Part Number: GRM188R71C394KA88D
footprint CAP-0603 (0603 (1608M) Capacitor)
pins: 1, 2

## GRM188R71E104KA01D
designator C?  Capacitance: 100nF  (hidden comment: *)
Capacitor, Ceramic (MLCC), 100nF, ±10%, 25V, X7R, ±10%, SMD 0603; Manufacturer: Murata Electronics; Manufacturer Part Number: GRM188R71E104KA01D
footprint CAP-0603 (0603 (1608M) Capacitor)
pins: 1, 2

## GRM188R71E105KA12D
designator C?  Capacitance: 1uF  (hidden comment: *)
Capacitor, Ceramic (MLCC), 1uF, ±10%, 25V, X7R, ±10%, SMD 0603; Manufacturer: Murata Electronics; Manufacturer Part Number: GRM188R71E105KA12D
footprint CAP-0603 (0603 (1608M) Capacitor)
pins: 1, 2

## GRM188R71E123KA01D
designator C?  Capacitance: 12nF  (hidden comment: *)
Capacitor, Ceramic (MLCC), 12nF, ±10%, 25V, X7R, ±10%, SMD 0603; Manufacturer: Murata Electronics; Manufacturer Part Number: GRM188R71E123KA01D
footprint CAP-0603 (0603 (1608M) Capacitor)
pins: 1, 2

## GRM188R71E154KA01D
designator C?  Capacitance: 150nF  (hidden comment: *)
Capacitor, Ceramic (MLCC), 150nF, ±10%, 25V, X7R, ±10%, SMD 0603; Manufacturer: Murata Electronics; Manufacturer Part Number: GRM188R71E154KA01D
footprint CAP-0603 (0603 (1608M) Capacitor)
pins: 1, 2

## GRM188R71E224KA88D
designator C?  Capacitance: 220nF  (hidden comment: *)
Capacitor, Ceramic (MLCC), 220nF, ±10%, 25V, X7R, ±10%, SMD 0603; Manufacturer: Murata Electronics; Manufacturer Part Number: GRM188R71E224KA88D
footprint CAP-0603 (0603 (1608M) Capacitor)
pins: 1, 2

## GRM188R71E474KA12D
designator C?  Capacitance: 470nF  (hidden comment: *)
Capacitor, Ceramic (MLCC), 470nF, ±10%, 25V, X7R, ±10%, SMD 0603; Manufacturer: Murata Electronics; Manufacturer Part Number: GRM188R71E474KA12D
footprint CAP-0603 (0603 (1608M) Capacitor)
pins: 1, 2

## GRM188R71E823KA01D
designator C?  Capacitance: 82nF  (hidden comment: *)
Capacitor, Ceramic (MLCC), 82nF, ±10%, 25V, X7R, ±10%, SMD 0603; Manufacturer: Murata Electronics; Manufacturer Part Number: GRM188R71E823KA01D
footprint CAP-0603 (0603 (1608M) Capacitor)
pins: 1, 2

## GRM188R71H102KA01D
designator C?  Capacitance: 1nF  (hidden comment: *)
Capacitor, Ceramic (MLCC), 1nF, ±10%, 50V, X7R, ±10%, SMD 0603; Manufacturer: Murata Electronics; Manufacturer Part Number: GRM188R71H102KA01D
footprint CAP-0603 (0603 (1608M) Capacitor)
pins: 1, 2

## GRM188R71H103KA01D
designator C?  Capacitance: 10nF  (hidden comment: *)
Capacitor, Ceramic (MLCC), 10nF, ±10%, 50V, X7R, ±10%, SMD 0603; Manufacturer: Murata Electronics; Manufacturer Part Number: GRM188R71H103KA01D
footprint CAP-0603 (0603 (1608M) Capacitor)
pins: 1, 2

## GRM188R71H104KA93D
designator C?  Capacitance: 100nF  (hidden comment: *)
Capacitor, Ceramic (MLCC), 100nF, ±10%, 50V, X7R, ±10%, SMD 0603; Manufacturer: Murata Electronics; Manufacturer Part Number: GRM188R71H104KA93D
footprint CAP-0603 (0603 (1608M) Capacitor)
pins: 1, 2

## GRM188R71H152KA01D
designator C?  Capacitance: 1.5nF  (hidden comment: *)
Capacitor, Ceramic (MLCC), 1.5nF, ±10%, 50V, X7R, ±10%, SMD 0603; Manufacturer: Murata Electronics; Manufacturer Part Number: GRM188R71H152KA01D
footprint CAP-0603 (0603 (1608M) Capacitor)
pins: 1, 2

## GRM188R71H153JA01D
designator C?  Capacitance: 15nF  (hidden comment: *)
Capacitor, Ceramic (MLCC), 15nF, ±5%, 50V, X7R, ±5%, SMD 0603; Manufacturer: Murata Electronics; Manufacturer Part Number: GRM188R71H153JA01D
footprint CAP-0603 (0603 (1608M) Capacitor)
pins: 1, 2

## GRM188R71H182KA01D
designator C?  Capacitance: 1.8nF  (hidden comment: *)
Capacitor, Ceramic (MLCC), 1.8nF, ±10%, 50V, X7R, ±10%, SMD 0603; Manufacturer: Murata Electronics; Manufacturer Part Number: GRM188R71H182KA01D
footprint CAP-0603 (0603 (1608M) Capacitor)
pins: 1, 2

## GRM188R71H222KA01D
designator C?  Capacitance: 2.2nF  (hidden comment: *)
Capacitor, Ceramic (MLCC), 2.2nF, ±10%, 50V, X7R, ±10%, SMD 0603; Manufacturer: Murata Electronics; Manufacturer Part Number: GRM188R71H222KA01D
footprint CAP-0603 (0603 (1608M) Capacitor)
pins: 1, 2

## GRM188R71H223KA01D
designator C?  Capacitance: 22nF  (hidden comment: *)
Capacitor, Ceramic (MLCC), 22nF, ±10%, 50V, X7R, ±10%, SMD 0603; Manufacturer: Murata Electronics; Manufacturer Part Number: GRM188R71H223KA01D
footprint CAP-0603 (0603 (1608M) Capacitor)
pins: 1, 2

## GRM188R71H224KAC4D
designator C?  Capacitance: 220nF  (hidden comment: *)
Capacitor, Ceramic (MLCC), 220nF, ±10%, 50V, X7R, ±10%, SMD 0603; Manufacturer: Murata Electronics; Manufacturer Part Number: GRM188R71H224KAC4D
footprint CAP-0603 (0603 (1608M) Capacitor)
pins: 1, 2

## GRM188R71H472KA01D
designator C?  Capacitance: 4.7nF  (hidden comment: *)
Capacitor, Ceramic (MLCC), 4.7nF, ±10%, 50V, X7R, ±10%, SMD 0603; Manufacturer: Murata Electronics; Manufacturer Part Number: GRM188R71H472KA01D
footprint CAP-0603 (0603 (1608M) Capacitor)
pins: 1, 2

## GRM188R72A222KA01D
designator C?  Capacitance: 2.2nF  (hidden comment: *)
Capacitor, Ceramic (MLCC), 2.2nF, ±10%, ±10%, SMD 0603; Manufacturer: Murata Electronics; Manufacturer Part Number: GRM188R72A222KA01D
footprint CAP-0603 (0603 (1608M) Capacitor)
pins: 1, 2

## GRM188R72A223KAC4D
designator C?  Capacitance: 22nF  (hidden comment: *)
Capacitor, Ceramic (MLCC), 22nF, ±10%, 100V, X7R, ±10%, SMD 0603; Manufacturer: Murata Electronics; Manufacturer Part Number: GRM188R72A223KAC4D
footprint CAP-0603 (0603 (1608M) Capacitor)
pins: 1, 2

## GRM188R72E331KW07D
designator C?  Capacitance: 330pF  (hidden comment: *)
Capacitor, Ceramic (MLCC), 330pF, ±10%, 250V, X7R, ±10%, SMD 0603; Manufacturer: Murata Electronics; Manufacturer Part Number: GRM188R72E331KW07D
footprint CAP-0603 (0603 (1608M) Capacitor)
pins: 1, 2

## GRM188R72E471KW07D
designator C?  Capacitance: 470pF  (hidden comment: *)
Capacitor, Ceramic (MLCC), 470pF, ±10%, 250V, X7R, ±10%, SMD 0603; Manufacturer: Murata Electronics; Manufacturer Part Number: GRM188R72E471KW07D
footprint CAP-0603 (0603 (1608M) Capacitor)
pins: 1, 2

## GRM188Z71A106KA73D
designator C?  Capacitance: 10uF  (hidden comment: *)
Capacitor, Ceramic (MLCC), 10uF, ±10%, 10V, X7R, ±10%, SMD 0603; Manufacturer: Murata Electronics; Manufacturer Part Number: GRM188Z71A106KA73D
footprint CAP-0603 (0603 (1608M) Capacitor)
pins: 1, 2

## GRM188Z71A106MA73D
designator C?  Capacitance: 10uF  (hidden comment: *)
Capacitor, Ceramic (MLCC), 10uF, ±20%, 10V, X7R, ±20%, SMD 0603; Manufacturer: Murata Electronics; Manufacturer Part Number: GRM188Z71A106MA73D
footprint CAP-0603 (0603 (1608M) Capacitor)
pins: 1, 2

## GRM188Z71C475KE21D
designator C?  Capacitance: 4.7uF  (hidden comment: *)
Capacitor, Ceramic (MLCC), 4.7uF, ±10%, 16V, X7R, ±10%, SMD 0603; Manufacturer: Murata Electronics; Manufacturer Part Number: GRM188Z71C475KE21D
footprint CAP-0603 (0603 (1608M) Capacitor)
pins: 1, 2

## GRM188Z71E225KE43D
designator C?  Capacitance: 2.2uF  (hidden comment: *)
Capacitor, Ceramic (MLCC), 2.2uF, ±10%, 25V, X7R, ±10%, SMD 0603; Manufacturer: Murata Electronics; Manufacturer Part Number: GRM188Z71E225KE43D
footprint CAP-0603 (0603 (1608M) Capacitor)
pins: 1, 2

## GRM1882C1H5R0CA01D
designator C?  Capacitance: 5pF  (hidden comment: *)
Capacitor, Ceramic (MLCC), 5pF, ±0.25pF, 50V, CH, ±0.25pF, SMD 0603; Manufacturer: Murata Electronics; Manufacturer Part Number: GRM1882C1H5R0CA01D
footprint CAP-0603 (0603 (1608M) Capacitor)
pins: 1, 2

## GRM1882C1H100JA01D
designator C?  Capacitance: 10pF  (hidden comment: *)
Capacitor, Ceramic (MLCC), 10pF, ±5%, 50V, CH, ±5%, SMD 0603; Manufacturer: Murata Electronics; Manufacturer Part Number: GRM1882C1H100JA01D
footprint CAP-0603 (0603 (1608M) Capacitor)
pins: 1, 2

## GRM1882C1H101JA01D
designator C?  Capacitance: 100pF  (hidden comment: *)
Capacitor, Ceramic (MLCC), 100pF, ±5%, 50V, CH, ±5%, SMD 0603; Manufacturer: Murata Electronics; Manufacturer Part Number: GRM1882C1H101JA01D
footprint CAP-0603 (0603 (1608M) Capacitor)
pins: 1, 2

## GRM1882C1H102JA01D
designator C?  Capacitance: 1nF  (hidden comment: *)
Capacitor, Ceramic (MLCC), 1nF, ±5%, 50V, CH, ±5%, SMD 0603; Manufacturer: Murata Electronics; Manufacturer Part Number: GRM1882C1H102JA01D
footprint CAP-0603 (0603 (1608M) Capacitor)
pins: 1, 2

## GRM1882C1H120JA01D
designator C?  Capacitance: 12pF  (hidden comment: *)
Capacitor, Ceramic (MLCC), 12pF, ±5%, 50V, CH, ±5%, SMD 0603; Manufacturer: Murata Electronics; Manufacturer Part Number: GRM1882C1H120JA01D
footprint CAP-0603 (0603 (1608M) Capacitor)
pins: 1, 2

## GRM1882C1H151JA01D
designator C?  Capacitance: 150pF  (hidden comment: *)
Capacitor, Ceramic (MLCC), 150pF, ±5%, 50V, CH, ±5%, SMD 0603; Manufacturer: Murata Electronics; Manufacturer Part Number: GRM1882C1H151JA01D
footprint CAP-0603 (0603 (1608M) Capacitor)
pins: 1, 2

## GRM1882C1H181JA01D
designator C?  Capacitance: 180pF  (hidden comment: *)
Capacitor, Ceramic (MLCC), 180pF, ±5%, 50V, CH, ±5%, SMD 0603; Manufacturer: Murata Electronics; Manufacturer Part Number: GRM1882C1H181JA01D
footprint CAP-0603 (0603 (1608M) Capacitor)
pins: 1, 2

## GRM1882C1H201JA01D
designator C?  Capacitance: 200pF  (hidden comment: *)
Capacitor, Ceramic (MLCC), 200pF, ±5%, 50V, CH, ±5%, SMD 0603; Manufacturer: Murata Electronics; Manufacturer Part Number: GRM1882C1H201JA01D
footprint CAP-0603 (0603 (1608M) Capacitor)
pins: 1, 2

## GRM1882C1H220JA01D
designator C?  Capacitance: 22pF  (hidden comment: *)
Capacitor, Ceramic (MLCC), 22pF, ±5%, 50V, CH, ±5%, SMD 0603; Manufacturer: Murata Electronics; Manufacturer Part Number: GRM1882C1H220JA01D
footprint CAP-0603 (0603 (1608M) Capacitor)
pins: 1, 2

## GRM1882C1H221JA01D
designator C?  Capacitance: 220pF  (hidden comment: *)
Capacitor, Ceramic (MLCC), 220pF, ±5%, 50V, CH, ±5%, SMD 0603; Manufacturer: Murata Electronics; Manufacturer Part Number: GRM1882C1H221JA01D
footprint CAP-0603 (0603 (1608M) Capacitor)
pins: 1, 2

## GRM1882C1H222JA01D
designator C?  Capacitance: 2.2nF  (hidden comment: *)
Capacitor, Ceramic (MLCC), 2.2nF, ±5%, 50V, CH, ±5%, SMD 0603; Manufacturer: Murata Electronics; Manufacturer Part Number: GRM1882C1H222JA01D
footprint CAP-0603 (0603 (1608M) Capacitor)
pins: 1, 2

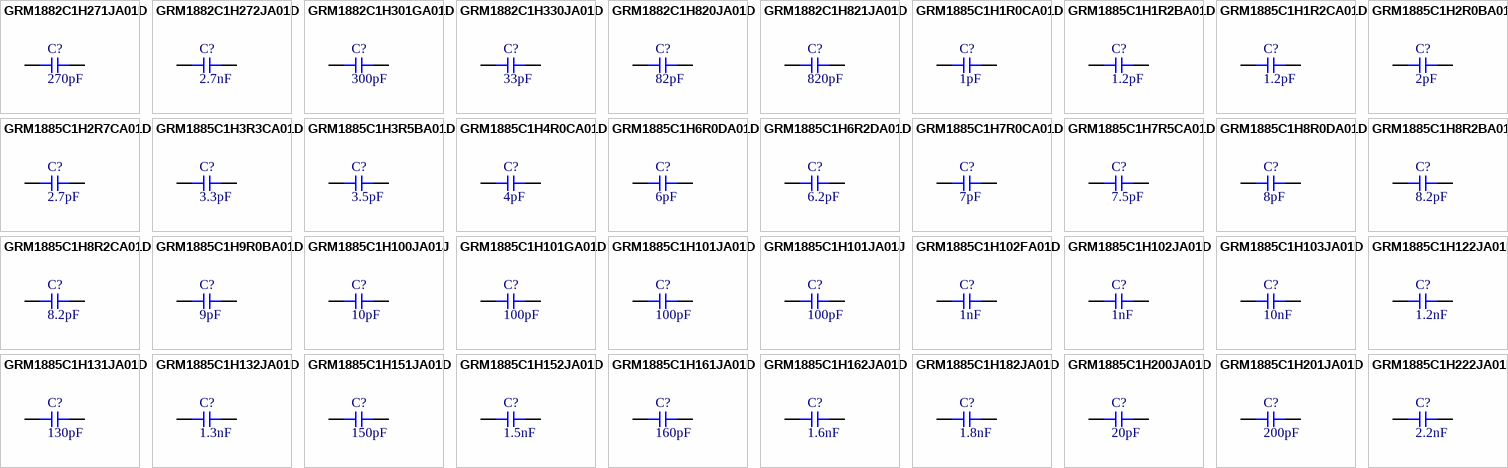
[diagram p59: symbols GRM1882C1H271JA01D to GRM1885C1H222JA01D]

## GRM1882C1H271JA01D
designator C?  Capacitance: 270pF  (hidden comment: *)
Capacitor, Ceramic (MLCC), 270pF, ±5%, 50V, CH, ±5%, SMD 0603; Manufacturer: Murata Electronics; Manufacturer Part Number: GRM1882C1H271JA01D
footprint CAP-0603 (0603 (1608M) Capacitor)
pins: 1, 2

## GRM1882C1H272JA01D
designator C?  Capacitance: 2.7nF  (hidden comment: *)
Capacitor, Ceramic (MLCC), 2.7nF, ±5%, 50V, CH, ±5%, SMD 0603; Manufacturer: Murata Electronics; Manufacturer Part Number: GRM1882C1H272JA01D
footprint CAP-0603 (0603 (1608M) Capacitor)
pins: 1, 2

## GRM1882C1H301GA01D
designator C?  Capacitance: 300pF  (hidden comment: *)
Capacitor, Ceramic (MLCC), 300pF, ±2%, 50V, CH, ±2%, SMD 0603; Manufacturer: Murata Electronics; Manufacturer Part Number: GRM1882C1H301GA01D
footprint CAP-0603 (0603 (1608M) Capacitor)
pins: 1, 2

## GRM1882C1H330JA01D
designator C?  Capacitance: 33pF  (hidden comment: *)
Capacitor, Ceramic (MLCC), 33pF, ±5%, 50V, CH, ±5%, SMD 0603; Manufacturer: Murata Electronics; Manufacturer Part Number: GRM1882C1H330JA01D
footprint CAP-0603 (0603 (1608M) Capacitor)
pins: 1, 2

## GRM1882C1H820JA01D
designator C?  Capacitance: 82pF  (hidden comment: *)
Capacitor, Ceramic (MLCC), 82pF, ±5%, 50V, CH, ±5%, SMD 0603; Manufacturer: Murata Electronics; Manufacturer Part Number: GRM1882C1H820JA01D
footprint CAP-0603 (0603 (1608M) Capacitor)
pins: 1, 2

## GRM1882C1H821JA01D
designator C?  Capacitance: 820pF  (hidden comment: *)
Capacitor, Ceramic (MLCC), 820pF, ±5%, 50V, CH, ±5%, SMD 0603; Manufacturer: Murata Electronics; Manufacturer Part Number: GRM1882C1H821JA01D
footprint CAP-0603 (0603 (1608M) Capacitor)
pins: 1, 2

## GRM1885C1H1R0CA01D
designator C?  Capacitance: 1pF  (hidden comment: *)
Capacitor, Ceramic (MLCC), 1pF, ±0.25pF, 50V, C0G, ±0.25pF, SMD 0603; Manufacturer: Murata Electronics; Manufacturer Part Number: GRM1885C1H1R0CA01D
footprint CAP-0603 (0603 (1608M) Capacitor)
pins: 1, 2

## GRM1885C1H1R2BA01D
designator C?  Capacitance: 1.2pF  (hidden comment: *)
Capacitor, Ceramic (MLCC), 1.2pF, ±0.1pF, 50V, C0G, ±0.1pF, SMD 0603; Manufacturer: Murata Electronics; Manufacturer Part Number: GRM1885C1H1R2BA01D
footprint CAP-0603 (0603 (1608M) Capacitor)
pins: 1, 2

## GRM1885C1H1R2CA01D
designator C?  Capacitance: 1.2pF  (hidden comment: *)
Capacitor, Ceramic (MLCC), 1.2pF, ±0.25pF, 50V, C0G, ±0.25pF, SMD 0603; Manufacturer: Murata Electronics; Manufacturer Part Number: GRM1885C1H1R2CA01D
footprint CAP-0603 (0603 (1608M) Capacitor)
pins: 1, 2

## GRM1885C1H2R0BA01D
designator C?  Capacitance: 2pF  (hidden comment: *)
Capacitor, Ceramic (MLCC), 2pF, ±0.1pF, 50V, C0G, ±0.1pF, SMD 0603; Manufacturer: Murata Electronics; Manufacturer Part Number: GRM1885C1H2R0BA01D
footprint CAP-0603 (0603 (1608M) Capacitor)
pins: 1, 2

## GRM1885C1H2R7CA01D
designator C?  Capacitance: 2.7pF  (hidden comment: *)
Capacitor, Ceramic (MLCC), 2.7pF, ±0.25pF, ±0.25pF, SMD 0603; Manufacturer: Murata Electronics; Manufacturer Part Number: GRM1885C1H2R7CA01D
footprint CAP-0603 (0603 (1608M) Capacitor)
pins: 1, 2

## GRM1885C1H3R3CA01D
designator C?  Capacitance: 3.3pF  (hidden comment: *)
Capacitor, Ceramic (MLCC), 3.3pF, ±0.25pF, 50V, C0G, ±0.25pF, SMD 0603; Manufacturer: Murata Electronics; Manufacturer Part Number: GRM1885C1H3R3CA01D
footprint CAP-0603 (0603 (1608M) Capacitor)
pins: 1, 2

## GRM1885C1H3R5BA01D
designator C?  Capacitance: 3.5pF  (hidden comment: *)
Capacitor, Ceramic (MLCC), 3.5pF, ±0.1pF, 50V, C0G, ±0.1pF, SMD 0603; Manufacturer: Murata Electronics; Manufacturer Part Number: GRM1885C1H3R5BA01D
footprint CAP-0603 (0603 (1608M) Capacitor)
pins: 1, 2

## GRM1885C1H4R0CA01D
designator C?  Capacitance: 4pF  (hidden comment: *)
Capacitor, Ceramic (MLCC), 4pF, ±0.25pF, 50V, C0G, ±0.25pF, SMD 0603; Manufacturer: Murata Electronics; Manufacturer Part Number: GRM1885C1H4R0CA01D
footprint CAP-0603 (0603 (1608M) Capacitor)
pins: 1, 2

## GRM1885C1H6R0DA01D
designator C?  Capacitance: 6pF  (hidden comment: *)
Capacitor, Ceramic (MLCC), 6pF, ±0.5pF, ±0.5pF, SMD 0603; Manufacturer: Murata Electronics; Manufacturer Part Number: GRM1885C1H6R0DA01D
footprint CAP-0603 (0603 (1608M) Capacitor)
pins: 1, 2

## GRM1885C1H6R2DA01D
designator C?  Capacitance: 6.2pF  (hidden comment: *)
Capacitor, Ceramic (MLCC), 6.2pF, ±0.5pF, 50V, C0G, ±0.5pF, SMD 0603; Manufacturer: Murata Electronics; Manufacturer Part Number: GRM1885C1H6R2DA01D
footprint CAP-0603 (0603 (1608M) Capacitor)
pins: 1, 2

## GRM1885C1H7R0CA01D
designator C?  Capacitance: 7pF  (hidden comment: *)
Capacitor, Ceramic (MLCC), 7pF, ±0.25pF, ±0.25pF, SMD 0603; Manufacturer: Murata Electronics; Manufacturer Part Number: GRM1885C1H7R0CA01D
footprint CAP-0603 (0603 (1608M) Capacitor)
pins: 1, 2

## GRM1885C1H7R5CA01D
designator C?  Capacitance: 7.5pF  (hidden comment: *)
Capacitor, Ceramic (MLCC), 7.5pF, ±0.25pF, 50V, C0G, ±0.25pF, SMD 0603; Manufacturer: Murata Electronics; Manufacturer Part Number: GRM1885C1H7R5CA01D
footprint CAP-0603 (0603 (1608M) Capacitor)
pins: 1, 2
